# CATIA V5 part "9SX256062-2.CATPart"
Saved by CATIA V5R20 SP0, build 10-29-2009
Part number: 9SX256062-2
Revision: ANY
Definition: UNKNOWN
Nomenclature: 9SX256062-2
Source: Unknown
Bounding box of the stored display mesh (mm): x -16 to 16, y -16 to 16, z 0 to 40
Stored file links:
  C:\Users\Utente\Desktop\IO LAVORO\3D X SITO CF\CUMSA\3D files SX.256062\SX 256062\9SX256062-2.CATPart
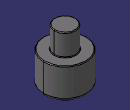
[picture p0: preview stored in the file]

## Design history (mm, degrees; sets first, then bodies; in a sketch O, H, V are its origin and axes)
Body1 "Redondeo5" (main body)
  Solid1: solid without history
